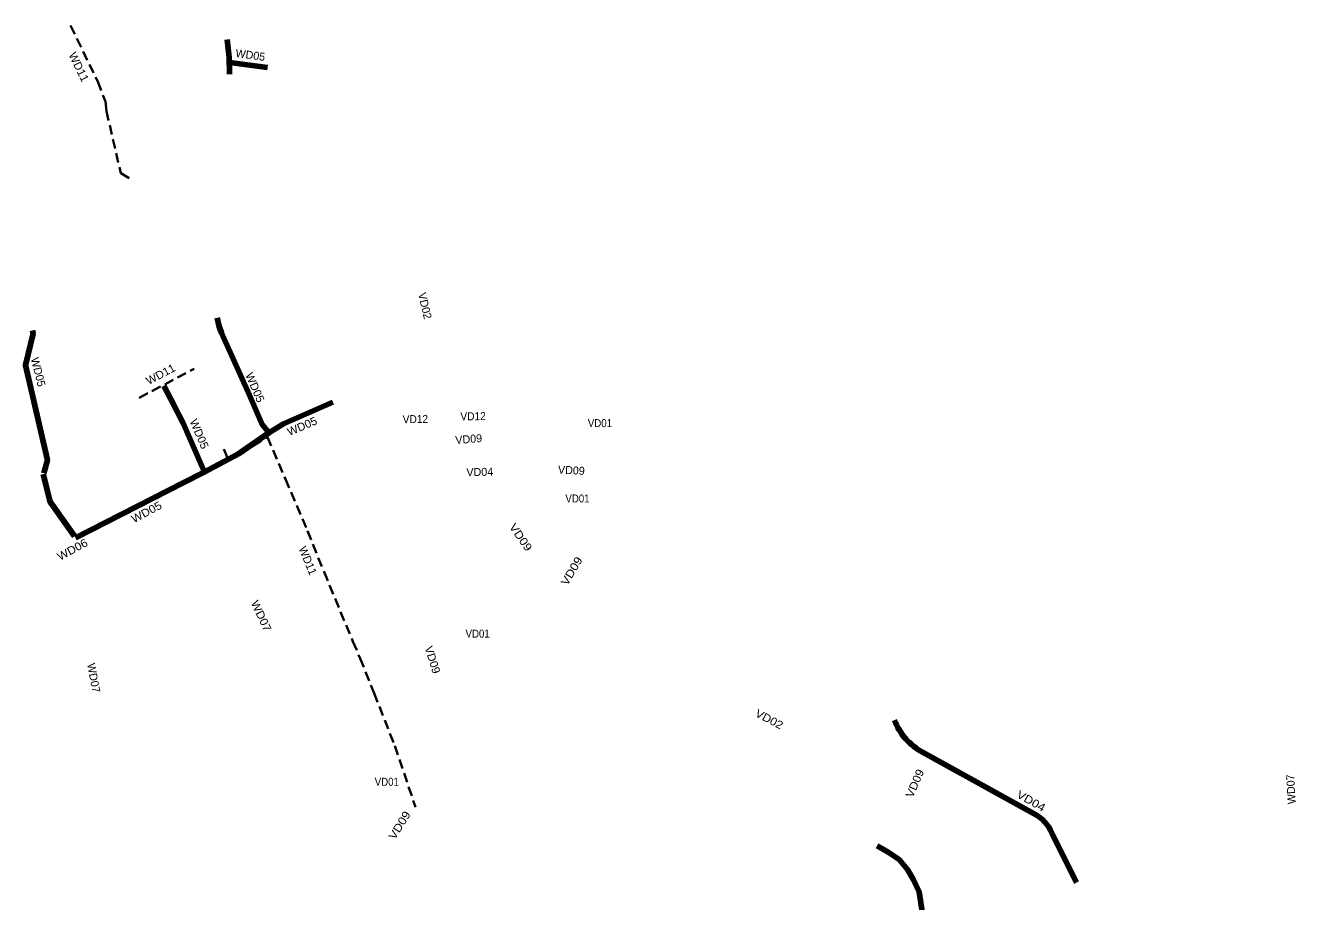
# Model space of a CAD drawing. Extents: x -650082 to -644047, y -1073232 to -1066669.
# Drawn here: x -648760 to -645586, y -1068858 to -1066669 of the extents above; entities that cross this region are included whole.
import ezdxf

# ---------------------------------------------------------------- set-up
doc = ezdxf.new("R2010")
doc.units = 0
doc.header["$LTSCALE"] = 8
doc.linetypes.add('MEDIUM_DASHED', pattern=[4.5, 3, -1.5])
for name, color, linetype in [('1', 7, 'Continuous'), ('14', 7, 'Continuous'), ('2', 7, 'Continuous'), ('20', 7, 'Continuous'), ('4', 7, 'Continuous'), ('5', 7, 'Continuous'), ('6', 7, 'Continuous'), ('7', 7, 'Continuous'), ('9', 7, 'Continuous')]:
    doc.layers.add(name, color=color, linetype=linetype)
for name, color, linetype, lineweight in [('11', 7, 'Continuous', 106), ('13', 7, 'MEDIUM_DASHED', 35), ('47', 7, 'Continuous', 106)]:
    doc.layers.add(name, color=color, linetype=linetype, lineweight=lineweight)

msp = doc.modelspace()

# ---------------------------------------------------------------- linework, layer by layer
at = {"layer": '11'}
for p, q in [((-646518.278, -1068484.783), (-646239.17, -1068638.65)), ((-646195.455, -1068687.016), (-646134.093, -1068810.478))]:
    msp.add_line(p, q, dxfattribs=at)
msp.add_lwpolyline([(-646581.274, -1069162.086), (-646543.734, -1069031.454), (-646526.307, -1068970.81), (-646520.034, -1068926.895), (-646519.124, -1068882.525), (-646527.13, -1068833.717), (-646541.089, -1068803.463), (-646555.823, -1068777.863), (-646576.76, -1068753.039), (-646603.929, -1068734.295), (-646632.204, -1068718.474)], dxfattribs=at)
for centre, radius, start, end in [((-646447.332, -1068351.964), 150.58, 200.6496, 241.891), ((-646287.447, -1068726.224), 100, 23.08426, 61.13296)]:
    msp.add_arc(centre, radius, start, end, dxfattribs=at)
at = {"layer": '13'}
msp.add_line((-648475.967, -1067599.594), (-648338.66, -1067527.2), dxfattribs=at)
for points in [[(-648647.496, -1066669.346), (-648579.736, -1066809.705), (-648560.474, -1066859.378), (-648557.753, -1066883.158), (-648521.948, -1067038.793), (-648497.158, -1067053.043)], [(-648264.598, -1067727.614), (-648252.736, -1067757.259), (-648155.436, -1067697.673), (-648110.6, -1067802.59), (-648055.22, -1067932.18), (-648014.17, -1068034.51), (-647986.62, -1068101.02), (-647941.71, -1068208.14), (-647923.95, -1068250.62), (-647888.92, -1068337.51), (-647837.19, -1068468.84), (-647785.355, -1068622.544)]]:
    msp.add_lwpolyline(points, dxfattribs=at)
at = {"layer": '47'}
msp.add_line((-648250.646, -1066761.805), (-648155.644, -1066774.286), dxfattribs=at)
for points in [[(-648255.756, -1066704.635), (-648250.791, -1066749.246), (-648250.308, -1066790.948)], [(-648280.799, -1067399.829), (-648276.458, -1067421.144), (-648270.075, -1067437.427), (-648264.51, -1067450.68), (-648249.006, -1067485.873), (-648200.759, -1067593.281), (-648168.435, -1067666.153), (-648150.996, -1067687.099)], [(-648742.866, -1067431.082), (-648741.14, -1067439.225), (-648760.37, -1067518.466), (-648705.539, -1067755.758), (-648713.989, -1067787.686)], [(-648414.419, -1067569.399), (-648397.13, -1067602.97), (-648382.03, -1067632.31), (-648376.02, -1067643.98), (-648366.45, -1067662.56), (-648312.613, -1067785.188)], [(-648635.024, -1067949.253), (-648365.832, -1067812.108), (-648315.36, -1067786.394), (-648228.068, -1067739.85), (-648151.632, -1067687.45), (-648115.068, -1067664.278), (-647992.06, -1067610.462)], [(-648715.867, -1067790.503), (-648698.498, -1067859.523), (-648637.584, -1067945.635)]]:
    msp.add_lwpolyline(points, dxfattribs=at)

# ---------------------------------------------------------------- texts
at = {"layer": '1', "width": 0.9}
for p in [(-647354.73, -1067672.938), (-647410.82, -1067861.136), (-647660.302, -1068198.804), (-647887.323, -1068568.836)]:
    msp.add_text('VD01', height=20, rotation=0.083, dxfattribs=at).set_placement(p)
at = {"layer": '14', "width": 1.05}
for rotation, p in [(295.942, (-648653.093, -1066742.467)), (27.775, (-648452.389, -1067567.821))]:
    msp.add_text('WD11', height=20, rotation=rotation, dxfattribs=at).set_placement(p)
at = {"layer": '14'}
msp.add_text('WD11', height=20, rotation=292.311, dxfattribs=at).set_placement((-648077.911, -1067975.767))
at = {"layer": '2'}
msp.add_text('VD02', height=20, rotation=283.284, dxfattribs=at).set_placement((-647779.255, -1067339.494))
at = {"layer": '2', "width": 1.1}
msp.add_text('VD02', height=20, rotation=332.288, dxfattribs=at).set_placement((-646938.71, -1068394.329))
at = {"layer": '20', "width": 0.95}
for p in [(-647817.467, -1067663.258), (-647673.194, -1067656.199)]:
    msp.add_text('VD12', height=20, rotation=0.939, dxfattribs=at).set_placement(p)
at = {"layer": '4'}
msp.add_text('VD04', height=20, rotation=1.14, dxfattribs=at).set_placement((-647658.076, -1067795.501))
at = {"layer": '4', "width": 1.15}
msp.add_text('VD04', height=20, rotation=330.29, dxfattribs=at).set_placement((-646285.411, -1068596.436))
at = {"layer": '5'}
for rotation, p in [(352.056, (-648236.269, -1066747.9)), (284.099, (-648747.005, -1067501.574))]:
    msp.add_text('WD05', height=20, rotation=rotation, dxfattribs=at).set_placement(p)
for rotation, width, p in [(293.365, 1.05, (-648211.332, -1067541.923)), (293.365, 1.05, (-648350.624, -1067658.036)), (23.241, 1.05, (-648100.74, -1067695.188)), (27.999, 1.1, (-648489.178, -1067912.995))]:
    msp.add_text('WD05', height=20, rotation=rotation, dxfattribs=dict(at, width=width)).set_placement(p)
at = {"layer": '6', "width": 1.1}
msp.add_text('WD06', height=20, rotation=28.611, dxfattribs=at).set_placement((-648673.978, -1068006.987))
at = {"layer": '7', "width": 1.1}
msp.add_text('WD07', height=20, rotation=295.111, dxfattribs=at).set_placement((-648197.555, -1068111.736))
at = {"layer": '7'}
for rotation, p in [(280.588, (-648606.359, -1068264.679)), (93.043, (-645585.871, -1068614.132))]:
    msp.add_text('WD07', height=20, rotation=rotation, dxfattribs=at).set_placement(p)
at = {"layer": '9'}
for rotation, p in [(4.598, (-647685.156, -1067715.389)), (356.921, (-647429.913, -1067788.745))]:
    msp.add_text('VD09', height=20, rotation=rotation, dxfattribs=at).set_placement(p)
for rotation, width, p in [(304.68, 1.15, (-647552.617, -1067922.041)), (59.386, 1.15, (-647406.292, -1068070.573)), (287.301, 1.05, (-647762.827, -1068223.473)), (66.391, 1.1, (-646543.229, -1068600.337)), (58.192, 1.15, (-647837.113, -1068705.38))]:
    msp.add_text('VD09', height=20, rotation=rotation, dxfattribs=dict(at, width=width)).set_placement(p)

doc.saveas('drawing.dxf')
